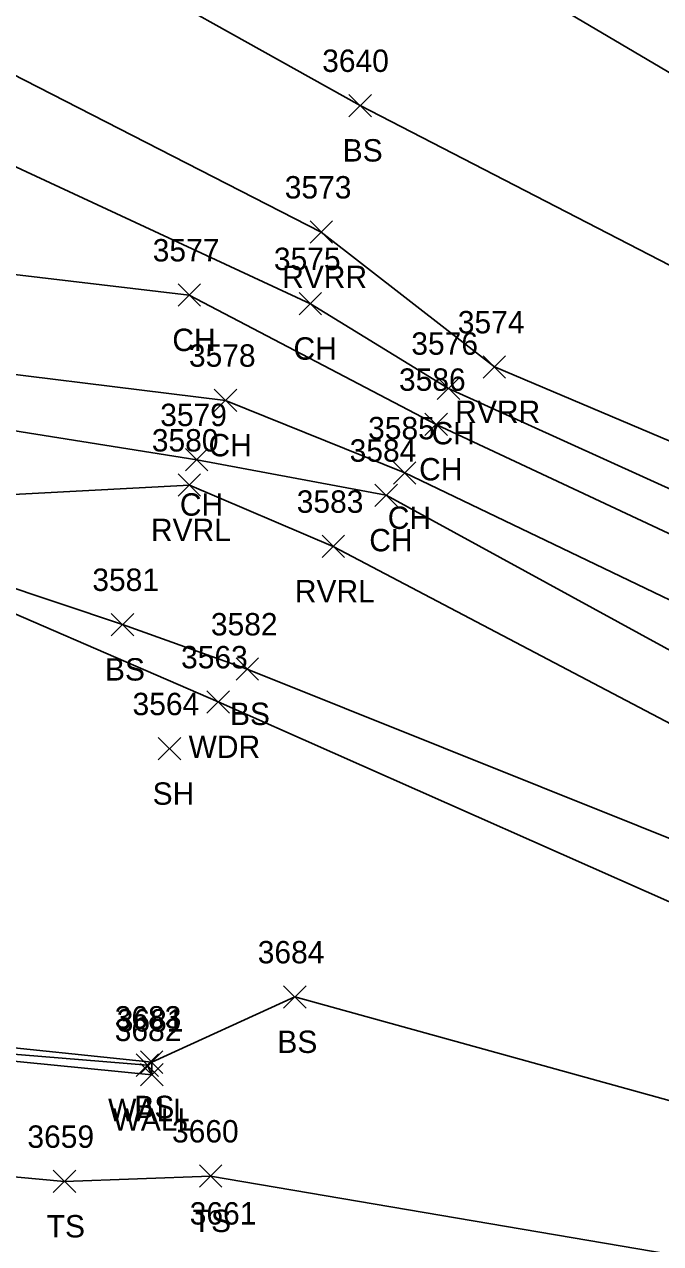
# Model space of a CAD drawing. Extents: x 1601151 to 1602912, y 499508 to 501770.
# Drawn here: x 1601741.8 to 1601798.6, y 500580.9 to 500689.8 of the extents above; entities that cross this region are included whole.
import ezdxf

# ---------------------------------------------------------------- set-up
doc = ezdxf.new("R2010")
doc.units = 0
for name, color, linetype in [('L_A', 7, 'Continuous'), ('L_I', 7, 'Continuous'), ('L_TIC', 7, 'Continuous'), ('LAWA', 7, 'Continuous'), ('LAWE', 7, 'Continuous'), ('LDEFAULT', 7, 'Continuous'), ('LELB', 7, 'Continuous'), ('LW', 7, 'Continuous')]:
    doc.layers.add(name, color=color, linetype=linetype)

msp = doc.modelspace()

# ---------------------------------------------------------------- linework, layer by layer
at = {"layer": 'L_TIC'}
for points in [[(1601770.8, 500681.56), (1601772.8, 500683.56)], [(1601772.8, 500681.56), (1601770.8, 500683.56)], [(1601767.33, 500670.26), (1601769.33, 500672.26)], [(1601769.33, 500670.26), (1601767.33, 500672.26)], [(1601755.55, 500664.64), (1601757.55, 500666.64)], [(1601757.55, 500664.64), (1601755.55, 500666.64)], [(1601766.36, 500663.87), (1601768.36, 500665.87)], [(1601768.36, 500663.87), (1601766.36, 500665.87)], [(1601782.77, 500658.22), (1601784.77, 500660.22)], [(1601784.77, 500658.22), (1601782.77, 500660.22)], [(1601778.68, 500656.31), (1601780.68, 500658.31)], [(1601780.68, 500656.31), (1601778.68, 500658.31)], [(1601758.78, 500655.24), (1601760.78, 500657.24)], [(1601760.78, 500655.24), (1601758.78, 500657.24)], [(1601777.58, 500653.09), (1601779.58, 500655.09)], [(1601779.58, 500653.09), (1601777.58, 500655.09)], [(1601756.22, 500649.94), (1601758.22, 500651.94)], [(1601758.22, 500649.94), (1601756.22, 500651.94)], [(1601774.77, 500648.76), (1601776.77, 500650.76)], [(1601776.77, 500648.76), (1601774.77, 500650.76)], [(1601755.56, 500647.67), (1601757.56, 500649.67)], [(1601757.56, 500647.67), (1601755.56, 500649.67)], [(1601773.12, 500646.76), (1601775.12, 500648.76)], [(1601775.12, 500646.76), (1601773.12, 500648.76)], [(1601768.4, 500642.2), (1601770.4, 500644.2)], [(1601770.4, 500642.2), (1601768.4, 500644.2)], [(1601749.59, 500635.22), (1601751.59, 500637.22)], [(1601751.59, 500635.22), (1601749.59, 500637.22)], [(1601760.73, 500631.25), (1601762.73, 500633.25)], [(1601762.73, 500631.25), (1601760.73, 500633.25)], [(1601758.13, 500628.31), (1601760.13, 500630.31)], [(1601760.13, 500628.31), (1601758.13, 500630.31)], [(1601753.79, 500624.13), (1601755.79, 500626.13)], [(1601755.79, 500624.13), (1601753.79, 500626.13)], [(1601764.97, 500601.97), (1601766.97, 500603.97)], [(1601766.97, 500601.97), (1601764.97, 500603.97)], [(1601751.82, 500595.88), (1601753.82, 500597.88)], [(1601753.82, 500595.88), (1601751.82, 500597.88)], [(1601752.2, 500596.15), (1601754.2, 500598.15)], [(1601754.2, 500596.15), (1601752.2, 500598.15)], [(1601752.21, 500595.03), (1601754.21, 500597.03)], [(1601754.21, 500595.03), (1601752.21, 500597.03)], [(1601744.42, 500585.5), (1601746.42, 500587.5)], [(1601746.42, 500585.5), (1601744.42, 500587.5)], [(1601757.45, 500585.98), (1601759.45, 500587.98)], [(1601759.45, 500585.98), (1601757.45, 500587.98)]]:
    msp.add_lwpolyline(points, dxfattribs=at)
at = {"layer": 'LAWA'}
for points in [[(1601593.12, 500801.88), (1601615.83, 500798.98), (1601635.32, 500780.93), (1601655.21, 500765.08), (1601678.73, 500755.01), (1601678.28, 500744.95), (1601691.76, 500735.44), (1601706.12, 500726.41), (1601725.16, 500712.06), (1601744.25, 500704.2), (1601769.86, 500702.95), (1601803.71, 500682.95)], [(1601689.18, 500639.33), (1601707.96, 500638.01), (1601732.6, 500640.81), (1601759.13, 500629.31)], [(1601759.13, 500629.31), (1601850.95, 500588.6)]]:
    msp.add_lwpolyline(points, dxfattribs=at)
at = {"layer": 'LAWE'}
for points in [[(1601318.62, 500789.62), (1601362.93, 500806.22), (1601394.46, 500804.48), (1601434.19, 500795.17), (1601527.96, 500788.91), (1601546.38, 500778.25), (1601558, 500777.29), (1601574.08, 500771.8), (1601598.01, 500757.12), (1601667.95, 500738.14), (1601705.28, 500715.12), (1601735.85, 500687.88), (1601768.33, 500671.26), (1601783.77, 500659.22)], [(1601306.18, 500751.33), (1601317.25, 500756.98), (1601367.83, 500763.3), (1601372.87, 500762.43), (1601412.18, 500735.73), (1601469.83, 500692.23), (1601501.36, 500678.91), (1601577.08, 500648.29), (1601592.03, 500648.06), (1601605.35, 500652.04), (1601618.61, 500651.39), (1601650.85, 500649.25), (1601686.37, 500649.48), (1601701.52, 500650.2), (1601728.46, 500647.17), (1601756.56, 500648.67), (1601769.4, 500643.2)], [(1601783.77, 500659.22), (1601885.49, 500616.1)], [(1601769.4, 500643.2), (1601859.42, 500595.83)]]:
    msp.add_lwpolyline(points, dxfattribs=at)
at = {"layer": 'LDEFAULT'}
for points in [[(1601337.45, 500787.94), (1601362.97, 500800.69), (1601393.84, 500792.74), (1601431.56, 500786.24), (1601466, 500759.52), (1601526, 500726.82), (1601566.27, 500697.9), (1601580.09, 500695.39), (1601593.87, 500695.15), (1601641.19, 500685.49), (1601672.03, 500699.21), (1601695.98, 500708.01), (1601703.42, 500706.03), (1601734.4, 500680.19), (1601767.36, 500664.87), (1601779.68, 500657.31)], [(1601339.09, 500785.52), (1601337.45, 500787.94), (1601364.5, 500789.17), (1601390.07, 500781.72), (1601419.33, 500750.23), (1601457.25, 500747.59), (1601513.71, 500700.8), (1601568.04, 500687.18), (1601598.22, 500676.18), (1601647.03, 500668.88), (1601695.93, 500672.79), (1601756.55, 500665.64), (1601778.58, 500654.09)], [(1601303.68, 500759.4), (1601367.74, 500774.76), (1601385.3, 500764.32), (1601413.55, 500740.04), (1601448.35, 500721.35), (1601503.88, 500682.57), (1601578.22, 500651.86), (1601591.68, 500650.62), (1601603.79, 500656.64), (1601648.59, 500654.17), (1601682.93, 500659.64), (1601726.96, 500654.03), (1601736.69, 500654.19), (1601757.22, 500650.94), (1601774.12, 500647.76)], [(1601731.84, 500659.69), (1601759.78, 500656.24), (1601775.77, 500649.76)], [(1601779.68, 500657.31), (1601877.14, 500613.04)], [(1601778.58, 500654.09), (1601873.7, 500609.5)], [(1601775.77, 500649.76), (1601868.99, 500605)], [(1601774.12, 500647.76), (1601862.83, 500599.24)]]:
    msp.add_lwpolyline(points, dxfattribs=at)
at = {"layer": 'LELB'}
for points in [[(1601558.48, 500782.72), (1601575.06, 500777.59), (1601597.78, 500761.54), (1601614.66, 500759.88), (1601621.4, 500771.94), (1601644.48, 500755.47), (1601669.06, 500742.24), (1601693.91, 500725.52), (1601707.66, 500718.53), (1601722.2, 500709.86), (1601744.29, 500697.94), (1601771.8, 500682.56), (1601891.41, 500620.78)], [(1601727.58, 500643.93), (1601750.59, 500636.22), (1601761.73, 500632.25)], [(1601761.73, 500632.25), (1601857.69, 500593.76)], [(1601595.51, 500601.97), (1601597.49, 500607.35), (1601613.84, 500605.41), (1601619.33, 500602.41), (1601618.89, 500614.96), (1601626.12, 500618.11), (1601628.38, 500608.44), (1601639.43, 500596.61), (1601678.53, 500593.27), (1601684.78, 500593.47), (1601700.02, 500593.11), (1601710.48, 500590.72), (1601727.34, 500588.15), (1601745.42, 500586.5), (1601758.45, 500586.98)], [(1601722.81, 500617.24), (1601727.53, 500609.78), (1601736.87, 500606.46), (1601737.93, 500605.89), (1601736.61, 500598.88), (1601753.2, 500597.15), (1601765.97, 500602.97)], [(1601765.97, 500602.97), (1601842.22, 500581.85)], [(1601753.2, 500597.15), (1601753.21, 500596.03)], [(1601758.45, 500586.98), (1601833.13, 500574.25)]]:
    msp.add_lwpolyline(points, dxfattribs=at)
at = {"layer": 'LW'}
msp.add_lwpolyline([(1601735.74, 500597.73), (1601735.76, 500598.27), (1601752.82, 500596.88), (1601753.21, 500596.03), (1601735.74, 500597.73)], dxfattribs=at)

# ---------------------------------------------------------------- texts
at = {"layer": 'L_A'}
for s, p in [('BS', (1601770.24, 500677.56)), ('RVRR', (1601764.84, 500666.26)), ('CH', (1601755.04, 500660.64)), ('CH', (1601765.85, 500659.87)), ('RVRR', (1601780.28, 500654.22)), ('CH', (1601778.17, 500652.31)), ('CH', (1601758.27, 500651.24)), ('CH', (1601777.06, 500649.09)), ('CH', (1601755.71, 500645.94)), ('CH', (1601774.26, 500644.76)), ('RVRL', (1601753.13, 500643.67)), ('CH', (1601772.61, 500642.76)), ('RVRL', (1601765.97, 500638.2)), ('BS', (1601749.03, 500631.22)), ('BS', (1601760.18, 500627.25)), ('WDR', (1601756.49, 500624.31)), ('SH', (1601753.28, 500620.13)), ('BS', (1601764.41, 500597.97)), ('WALL', (1601749.31, 500591.88)), ('BS', (1601751.65, 500592.15)), ('WALL', (1601749.7, 500591.03)), ('TS', (1601743.83, 500581.5)), ('TS', (1601756.86, 500581.98))]:
    msp.add_text(s, height=2, dxfattribs=at).set_placement(p)
at = {"layer": 'L_I'}
for s, p in [('3640', (1601768.41, 500685.56)), ('3573', (1601765.07, 500674.26)), ('3577', (1601753.29, 500668.64)), ('3575', (1601764.1, 500667.87)), ('3574', (1601780.51, 500662.22)), ('3576', (1601776.36, 500660.31)), ('3578', (1601756.52, 500659.24)), ('3586', (1601775.26, 500657.09)), ('3579', (1601753.96, 500653.94)), ('3585', (1601772.51, 500652.76)), ('3580', (1601753.21, 500651.67)), ('3584', (1601770.86, 500650.76)), ('3583', (1601766.14, 500646.2)), ('3581', (1601747.9, 500639.22)), ('3582', (1601758.48, 500635.25)), ('3563', (1601755.82, 500632.31)), ('3564', (1601751.49, 500628.13)), ('3684', (1601762.66, 500605.97)), ('3683', (1601749.9, 500600.15)), ('3681', (1601750.08, 500599.88)), ('3682', (1601749.9, 500599.03)), ('3660', (1601755.01, 500589.98)), ('3659', (1601742.11, 500589.5)), ('3661', (1601756.59, 500582.65))]:
    msp.add_text(s, height=2, dxfattribs=at).set_placement(p)

doc.saveas('drawing.dxf')
